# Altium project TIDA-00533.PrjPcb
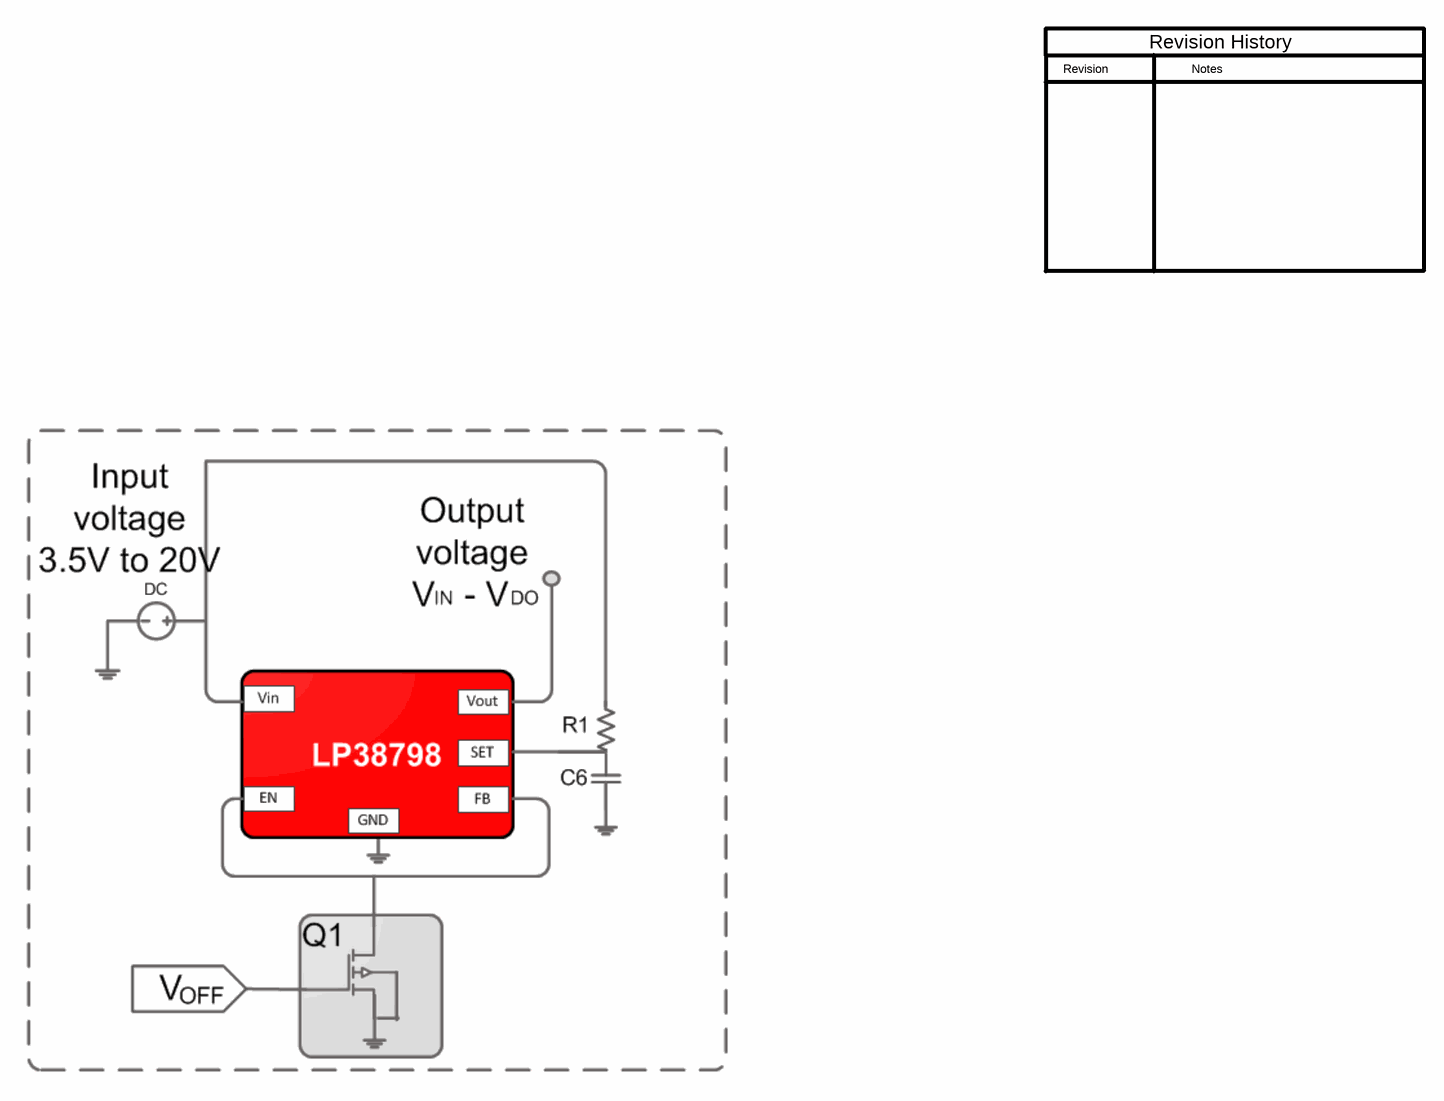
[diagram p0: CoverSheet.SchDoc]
CopyrightYear: 2015; EVM_Orderable: N/A; PCB_Layout: Jacen Schadler/A. Carvajales; PCB_Rev: E1; PRJ_Customer: Public Release; PRJ_Engineer: Done Jones/A. Carvajales; PRJ_Number: TIDA-00533; PRJ_Title: TIDA-00533; SCH_Rev: E1; TechSupport: http://www.ti.com/support; TID: 00533
3 sheets, 24 parts. Net scope: global (net labels, ports and power ports of the same name join across sheets).
Board file: TID.PcbDoc
Sheets:
  CoverSheet.SchDoc
  BlankSheet.SchDoc
  TID_Hardware.SchDoc

## Sheet CoverSheet.SchDoc
size 431 x 279 mm; Date: Not shown in title block; ApprovedBy: Not shown in title block; CheckedBy: Not shown in title block; Author: Not shown in title block; CompanyName: Not shown in title block; Engineer: Not shown in title block; Organization: Not shown in title block; Address1: Not shown in title block; Address2: Not shown in title block; Address3: Not shown in title block; Address4: Not shown in title block; DocumentNumber: 1; Revision: Use project parameter SCH_Rev; SheetNumber: 1; SheetTotal: 3; PageSetup: Record=PageOptions¦CenterHorizontal=True¦CenterVertical=True¦PrintScale=1.00¦XCorrection=1.00¦YCorrection=1.00¦PrintKind=0¦BorderSize=5000000¦LeftOffset=0¦BottomOffset=0¦Orientation=2¦PaperLength=1000¦PaperWidth=1000¦Scale=100¦PaperSource=15¦PrintQuality=600¦MediaType=1¦DitherType=10¦PaperKind=Letter¦PrintScaleMode=1

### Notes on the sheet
- Revision
- Notes
- Revision History

## Sheet BlankSheet.SchDoc
size 431 x 279 mm; Date: Not shown in title block; ApprovedBy: Not shown in title block; CheckedBy: Not shown in title block; Author: Not shown in title block; CompanyName: Not shown in title block; Engineer: Not shown in title block; Organization: Not shown in title block; Address1: Not shown in title block; Address2: Not shown in title block; Address3: Not shown in title block; Address4: Not shown in title block; DocumentNumber: 1; Revision: Use project parameter SCH_Rev; SheetNumber: 2; SheetTotal: 3; PageSetup: Record=PageOptions¦CenterHorizontal=True¦CenterVertical=True¦PrintScale=1.00¦XCorrection=1.00¦YCorrection=1.00¦PrintKind=0¦BorderSize=5000000¦LeftOffset=0¦BottomOffset=0¦Orientation=2¦PaperLength=1000¦PaperWidth=1000¦Scale=100¦PaperSource=15¦PrintQuality=600¦MediaType=1¦DitherType=10¦PaperKind=Letter¦PrintScaleMode=1
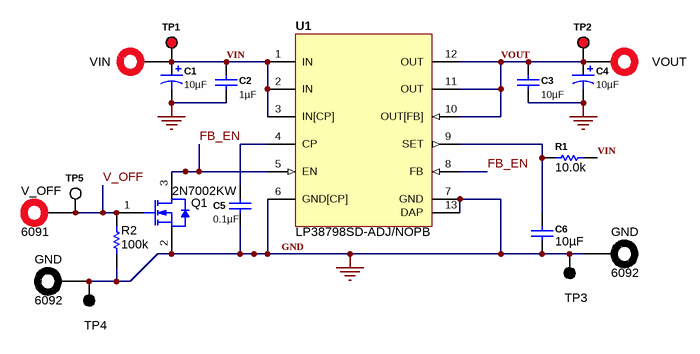
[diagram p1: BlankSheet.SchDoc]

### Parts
(Parts that share a designator on the sheet are numbered #1, #2 ... from top to bottom, then left to right.)
C1  ValueDisplayed: 10µF  [6032-28]  (hidden comment: TPSC106K025R0500)
C2  ValueDisplayed: 1µF  [1206L]  (hidden comment: 12103C105KAT2A)
C3  ValueDisplayed: 10µF  [1206L]  (hidden comment: 1206YC106KAT2A)
C4  ValueDisplayed: 10µF  [3216-18]  (hidden comment: TPSA106K010R0900)
C5  ValueDisplayed: 0.1µF  [0805L]  (hidden comment: 08055C104KAT2A)
C6  ValueDisplayed: 10µF  [1206]  (hidden comment: GRM31CR71C106KAC7L)
GND#1  6092  [6092]
GND#2  6092  [6092]
Q1  2N7002KW  [SOT-323]
R1  ValueDisplayed: 10.0k  [0805L]  (hidden comment: CRCW080510K0FKEA)
R2  ValueDisplayed: 100k  [0603]  (hidden comment: RC0603FR-07100KL)
TP1  5000  [Keystone5000]  (value not drawn)
TP2  5000  [Keystone5000]  (value not drawn)
TP3  5001  [Keystone5001]  (value not drawn)
TP4  5001  [Keystone5001]  (value not drawn)
TP5  5002  [Keystone5002]  (value not drawn)
U1  LP38798SD-ADJ/NOPB  [DNT0012B]
V_OFF  6091  [6091]
VIN  6091  [6091]  (value not drawn)
VOUT  6091  [6091]  (value not drawn)

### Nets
GND: C1.2(-) C2.2 C3.2 C4.2(-) C5.2 C6.2 GND#1.1 GND#2.1 Q1.2(S) R2.1 TP3.1 TP4.1 U1.6(GND[CP]) U1.7(GND) U1.13(DAP)
FB_EN: Q1.3(D) U1.5(EN) U1.8(FB)
V_OFF: Q1.1(G) R2.2 TP5.1 V_OFF.1
VIN: C1.1(+) C2.1 R1.1 TP1.1 U1.1(IN) U1.2(IN) U1.3(IN[CP]) VIN.1
VOUT: C3.1 C4.1(+) TP2.1 U1.10(OUT[FB]) U1.11(OUT) U1.12(OUT) VOUT.1
NetC5_1: C5.1 U1.4(CP)
NetC6_1: C6.1 R1.2 U1.9(SET)

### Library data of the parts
C1 = TPSC106K025R0500: CAP, TANT, 10uF, 25V, +/-10%, 0.5 ohm, 6032-28 SMD; Manufacturer: AVX; Polarized: Y; CompType: Capacitor; U/M: EA; Cap_F: 0.00001; Tolerance_%: 10; Value1: 0.5 ohm; VDC_V: 25; ESR_Ohm: 0.5; IRMS_A: 0.422; TaMin_C: -55; TaMax_C: 125; Cap_Case: C
C2 = 12063C105KAT2A: CAP, MLCC, 1uF, 25V, +/-10%, X7R, 1206; Manufacturer: AVX; Polarized: N; CompType: Capacitor; U/M: EA; Cap_F: 0.000001; Tolerance_%: 10; ESR_Ohm: 0.013; VDC_V: 25; TaMin_C: -55; TaMax_C: 125; Cap_Case: 1206
C3 = C3216X5R1C106M: CAP, MLCC, 10uF, 16V, +/-10%, X7R, 1206; Manufacturer: AVX; Polarized: N; CompType: Capacitor; U/M: EA; Cap_F: 0.00001; Tolerance_%: 10; VDC_V: 16; IRMS_A: 2.7; TaMin_C: -55; TaMax_C: 85; Cap_Case: 1206
C4 = TPSA106K010R0900: CAP, TANT, 10uF, 10V, +/-10%, 0.9 ohm, 3216-18 SMD; Manufacturer: AVX; Polarized: Y; CompType: Capacitor; U/M: EA; Cap_F: 0.00001; Tolerance_%: 10; Value1: 0.9 ohm; ESR_Ohm: 0.9; IRMS_A: 0.26; TaMin_C: -55; TaMax_C: 125; Cap_Case: A
C5 = 08055C104KAT2A: CAP, CERM, 0.1uF, 50V, +/-10%, X7R, 0805; Manufacturer: AVX; Polarized: N; CompType: Capacitor; U/M: EA; Cap_F: 0.0000001; Tolerance_%: 10; ESR_Ohm: 0.024; Value1: 0.024 ohm; VDC_V: 50; TaMin_C: -55; TaMax_C: 125; Cap_Case: 0805
C6 = GRM31CR71C106KAC7L: CAP, CERM, 10 µF, 16 V, +/- 10%, X7R, 1206; Manufacturer: MuRata; CompType: Capacitor; Value: 10uF; Tolerance_%: 10; Value1: Unknown; Value2: 16V; VDC_V: 16; U/M: EA; Polarized: N; Cap_F: 0.00001; TaMin_C: -55; TaMax_C: 125
GND#1 GND#2 = 6092: Standard Banana Jack, Insulated, Black; Manufacturer: Keystone; SymbolCreator: a0412235; CompType: Connector; U/M: EA
Q1 = 2N7002KW: MOSFET, N-CH, 60 V, 0.31 A, SOT-323; Manufacturer: Fairchild Semiconductor; Alternate Manufacturer: None; U/M: EA; ChType: N; Value: 60V; VdsMax_V: 60; Value1: 1.6 ohm; Rdson45_ohm: 1.6; Value2: ? nC; Vgs_V: 2.1; IdsMax_A: 0.31
R1 = CRCW080510K0FKEA: RES, 10.0 k, 1%, 0.125 W, 0805; Manufacturer: Vishay-Dale; CompType: Resistor; Value: 10.0k; Res_ohm: 10000; Value_Code: 10k0; Tolerance_%: 1; Power_W: 0.125; Value2: 0.125W; VDC_V: 150; TempCo: 100 ppm/C; EIA_Code: E96; U/M: EA
R2 = RC0603FR-07100KL: RES, 100 k, 1%, 0.1 W, 0603; Manufacturer: Yageo America; CompType: Resistor; Value: 100k; Res_ohm: 100000; Tolerance_%: 1; Power_W: 0.1; Value2: 0.1W; VDC_V: 150; TempCo: 200 ppm/C; EIA_Code: E96; U/M: EA
TP1 TP2 = 5000: Test Point, TH, Miniature, Red; Manufacturer: Keystone Electronics; CompType: Test Point Loop; U/M: EA
TP3 TP4 = 5001: Test Point, Miniature, Black, TH; Manufacturer: Keystone; CompType: Test Point Loop; U/M: EA
TP5 = 5002: Test Point, TH, Miniature, White; Manufacturer: Keystone; CompType: Test Point Loop; U/M: EA
U1 = LP38798SD-ADJ/NOPB: Ultra Low Noise, 800 mA Linear Voltage Regulator for RF/Analog Circuits, DNT0012B; Alternate Manufacturer: Texas Instruments; CompType: IC; SymbolCreator: a0799628; U/M: EA
V_OFF = 6091: Standard Banana Jack, Insulated, Red; Manufacturer: Keystone; SymbolCreator: a0412235; CompType: Connector; U/M: EA
VIN VOUT = 6091: Standard Banana Jack, Insulated, Red; Manufacturer: Keystone; SymbolCreator: codlsc; CompType: Connector; U/M: EA

## Sheet TID_Hardware.SchDoc
size 431 x 279 mm; Date: Not shown in title block; ApprovedBy: Not shown in title block; CheckedBy: Not shown in title block; Author: Not shown in title block; CompanyName: Not shown in title block; Engineer: Not shown in title block; Organization: Not shown in title block; Address1: Not shown in title block; Address2: Not shown in title block; Address3: Not shown in title block; Address4: Not shown in title block; DocumentNumber: 1; Revision: Use project parameter SCH_Rev; SheetNumber: 3; SheetTotal: 3; PageSetup: Record=PageOptions¦CenterHorizontal=True¦CenterVertical=True¦PrintScale=1.00¦XCorrection=1.00¦YCorrection=1.00¦PrintKind=0¦BorderSize=5000000¦LeftOffset=0¦BottomOffset=0¦Orientation=2¦PaperLength=1000¦PaperWidth=1000¦Scale=100¦PaperSource=15¦PrintQuality=600¦MediaType=1¦DitherType=10¦PaperKind=Letter¦PrintScaleMode=1
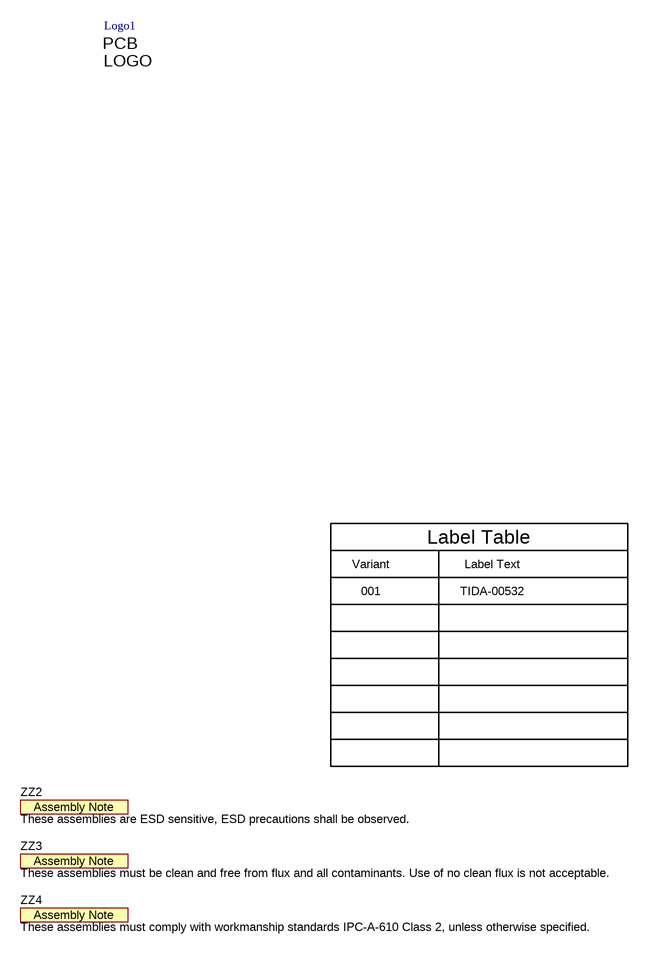
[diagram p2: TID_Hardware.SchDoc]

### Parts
Logo1  Texas Instruments  [TI_Symbol_Overlay_Small]  (value not drawn)  (no BOM)
ZZ2  These assemblies are ESD sensitive, ESD precautions shall be observed.  [AssemblyNote]  (no BOM)
ZZ3  These assemblies must be clean and free from flux and all contaminants. Use of no clean flux is not acceptable.  [AssemblyNote]  (no BOM)
ZZ4  These assemblies must comply with workmanship standards IPC-A-610 Class 2, unless otherwise specified.  [AssemblyNote]  (no BOM)

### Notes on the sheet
- Variant
- Label Table
- Label Text
- 001
- TIDA-00532

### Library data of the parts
Logo1 = TI_Logo: Texas Instrument Corporate Signature; SymbolCreator: codlsc
ZZ2-ZZ4 = AssemblyNote: SymbolCreator: codlsc

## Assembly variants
001: not fitted FID1 FID2 FID3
